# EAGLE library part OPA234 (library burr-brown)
Operational Amplifiers Low Power, Precision, Single-Supply
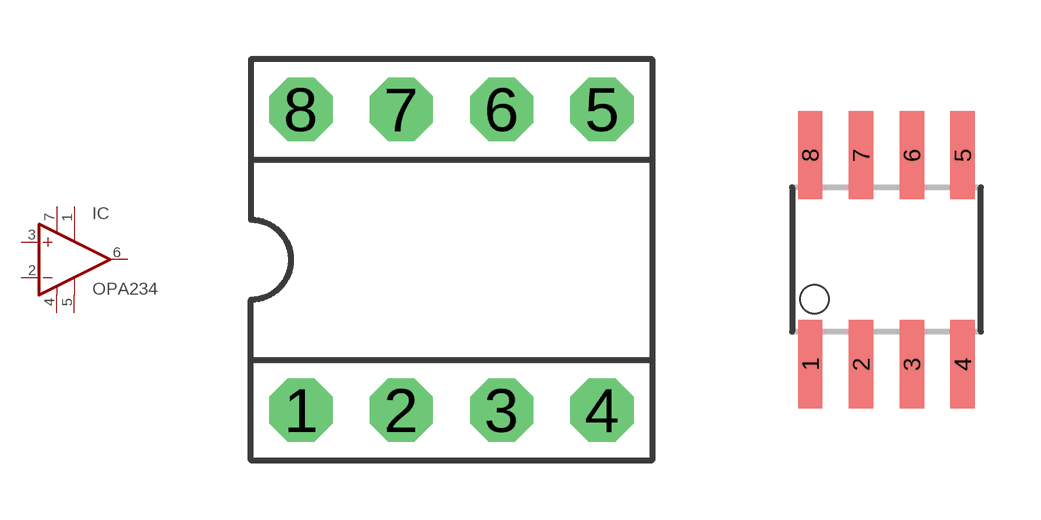
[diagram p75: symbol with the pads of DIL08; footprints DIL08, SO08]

Designator prefix IC

## OPA234P (OC_FARNELL: unknown; OC_NEWARK: unknown)  [DIL08]
1  TRIM1  pas
2  -IN  in
3  +IN  in
4  V-  pwr
5  TRIM2  pas
6  OUT  out
7  V+  pwr

## OPA234U (MF: TEXAS INSTRUMENT CONNECTORS; MPN: OPA234U; OC_FARNELL: 1648695; OC_NEWARK: 75C4693)  [SO08]
Pads as for DIL08

## Footprint DIL08 (pad centres in mm)
Dual In Line
drill 0.813 pad 1.6 octagon: 1 -3.81,-3.81; 2 -1.27,-3.81; 3 1.27,-3.81; 4 3.81,-3.81; 5 3.81,3.81; 6 1.27,3.81; 7 -1.27,3.81; 8 -3.81,3.81

## Footprint SO08 (pad centres in mm)
Small Outline Package
smd 0.61 x 2.21: 1 -1.905,-2.616; 2 -0.635,-2.616; 3 0.635,-2.616; 4 1.905,-2.616; 5 1.905,2.616; 6 0.635,2.616; 7 -0.635,2.616; 8 -1.905,2.616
